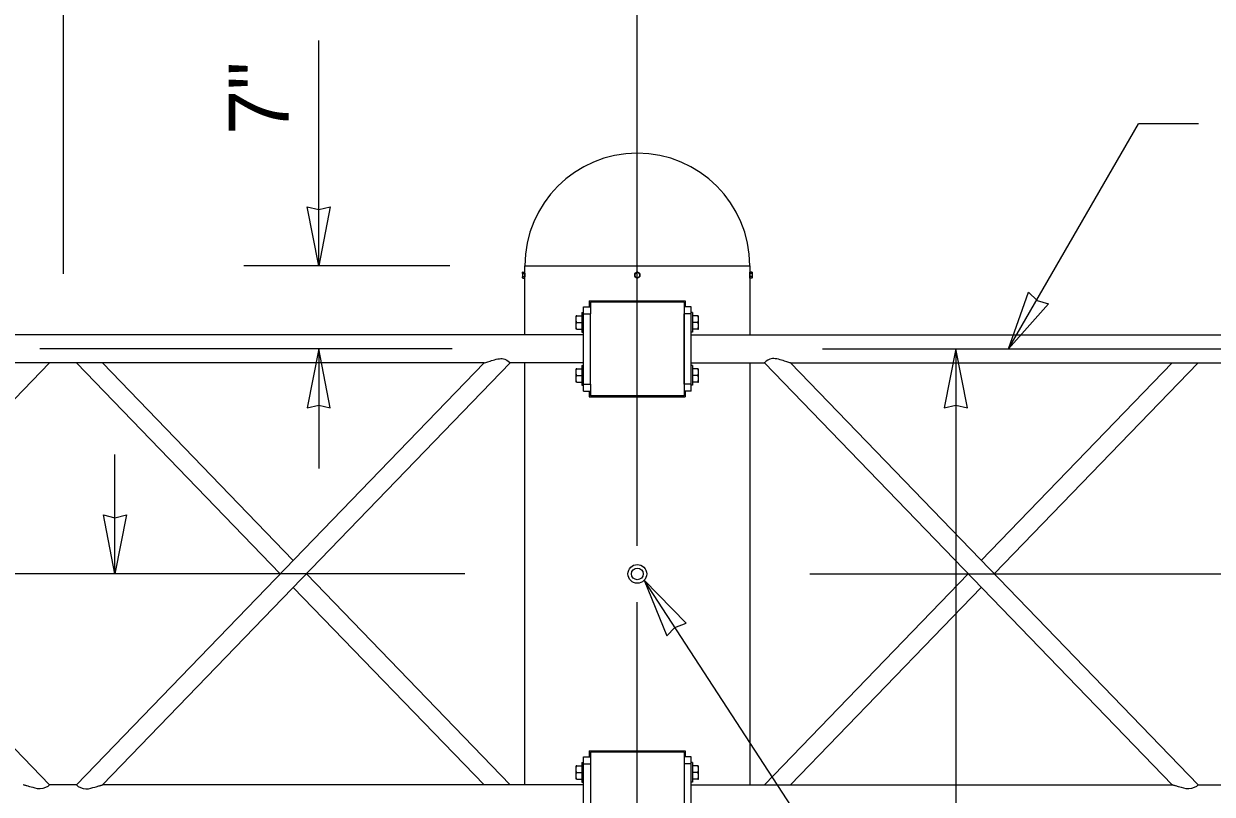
# Model space of a CAD drawing. Extents: x 99862 to 104211, y 98939 to 111076.
# Drawn here: x 101176.8 to 101493.9, y 104337.2 to 104542.6 of the extents above; entities that cross this region are included whole.
import ezdxf

# ---------------------------------------------------------------- set-up
doc = ezdxf.new("R2010")
doc.units = 0
for name, color, linetype in [('Level 15', 7, 'Continuous'), ('Level 20', 7, 'Continuous'), ('Level 3', 7, 'Continuous'), ('Level 4', 7, 'Continuous'), ('Level 5', 7, 'Continuous'), ('Level 6', 7, 'Continuous'), ('Level 9', 7, 'Continuous')]:
    doc.layers.add(name, color=color, linetype=linetype)

msp = doc.modelspace()

# ---------------------------------------------------------------- linework, layer by layer
at = {"layer": 'Level 15'}
for p, q in [((101187.43, 104475.89), (101187.43, 104720.89)), ((101340.5, 104403.39), (101340.5, 104615.2)), ((101255.5, 104478.08), (101255.5, 104538.08)), ((101439.57, 104455.89), (101474.21, 104515.89)), ((101490.21, 104515.89), (101474.21, 104515.89)), ((101290.5, 104478.08), (101235.5, 104478.08)), ((101291.12, 104455.89), (101181.12, 104455.89)), ((101255.5, 104455.89), (101255.5, 104424.01)), ((101389.87, 104455.89), (101540.24, 104455.89)), ((101425.5, 104455.89), (101425.5, 103662.4)), ((101201.12, 104395.89), (101201.12, 104427.77)), ((101294.5, 104395.89), (100703.11, 104395.89)), ((101386.5, 104395.89), (102303.88, 104395.89)), ((101519.55, 104122.56), (101342.34, 104394.21)), ((101340.5, 103587.9), (101340.5, 104388.39))]:
    msp.add_line(p, q, dxfattribs=at)
for points in [[(101255.5, 104478.08), (101252.41, 104493.8), (101255.5, 104493.08), (101258.58, 104493.8)], [(101439.57, 104455.89), (101444.88, 104471.01), (101447.17, 104468.82), (101450.2, 104467.88)], [(101255.5, 104455.89), (101252.41, 104440.17), (101255.5, 104440.89), (101258.58, 104440.17)], [(101425.5, 104455.89), (101422.41, 104440.17), (101425.5, 104440.89), (101428.58, 104440.17)], [(101201.12, 104395.89), (101198.04, 104411.62), (101201.12, 104410.89), (101204.21, 104411.62)], [(101342.34, 104394.21), (101348.35, 104379.35), (101350.54, 104381.65), (101353.52, 104382.72)]]:
    msp.add_lwpolyline(points, close=True, dxfattribs=at)
at = {"layer": 'Level 20'}
for p, q in [((101129.28, 104395.89), (101183.68, 104452.14)), ((101245.25, 104395.89), (101190.85, 104452.14)), ((101248.72, 104399.49), (101197.8, 104452.14)), ((101432.27, 104399.49), (101483.19, 104452.14)), ((101435.75, 104395.89), (101490.15, 104452.14)), ((101306.6, 104339.64), (101252.2, 104395.89)), ((101374.4, 104339.64), (101428.79, 104395.89)), ((101299.64, 104339.64), (101248.72, 104392.3)), ((101381.35, 104339.64), (101432.27, 104392.3))]:
    msp.add_line(p, q, dxfattribs=at)
at = {"layer": 'Level 3'}
for p, q in [((101310.5, 104476.39), (101310.5, 104478.08)), ((101370.5, 104478.08), (101370.5, 104459.64)), ((101310.5, 104459.64), (101310.5, 104474.77)), ((101327.68, 104468.7), (101327.68, 104467.14)), ((101327.68, 104468.7), (101353.31, 104468.7)), ((101353.31, 104468.7), (101353.31, 104467.14)), ((101310.5, 104339.64), (101310.5, 104452.14)), ((101370.5, 104452.14), (101370.5, 104339.64)), ((101327.68, 104444.64), (101327.68, 104443.08)), ((101327.68, 104443.08), (101353.31, 104443.08)), ((101353.31, 104444.64), (101353.31, 104443.08)), ((101327.68, 104348.7), (101353.31, 104348.7)), ((101327.68, 104348.7), (101327.68, 104347.14)), ((101353.31, 104348.7), (101353.31, 104347.14))]:
    msp.add_line(p, q, dxfattribs=at)
for radius in [2.5, 1.56]:
    msp.add_circle((101340.5, 104395.89), radius, dxfattribs=at)
for points in [[(101310.5, 104476.05), (101310.5, 104476.05), (101310.5, 104476.05), (101310.5, 104476.04), (101310.5, 104476.04), (101310.5, 104476.02), (101310.5, 104476), (101310.5, 104475.98), (101310.5, 104475.95), (101310.5, 104475.91), (101310.5, 104475.87), (101310.5, 104475.83), (101310.5, 104475.78), (101310.5, 104475.73), (101310.5, 104475.68), (101310.5, 104475.63), (101310.5, 104475.58), (101310.5, 104475.52), (101310.5, 104475.47), (101310.5, 104475.42), (101310.5, 104475.37), (101310.5, 104475.33), (101310.5, 104475.28), (101310.5, 104475.24), (101310.5, 104475.21), (101310.5, 104475.18), (101310.5, 104475.15), (101310.5, 104475.14), (101310.5, 104475.12), (101310.5, 104475.11), (101310.5, 104475.11)], [(101370.5, 104476.05), (101370.5, 104476.05), (101370.5, 104476.05), (101370.5, 104476.04), (101370.5, 104476.04), (101370.5, 104476.02), (101370.5, 104476), (101370.5, 104475.98), (101370.5, 104475.95), (101370.49, 104475.91), (101370.49, 104475.87), (101370.49, 104475.83), (101370.49, 104475.78), (101370.49, 104475.73), (101370.49, 104475.68), (101370.49, 104475.63), (101370.49, 104475.58), (101370.49, 104475.52), (101370.49, 104475.47), (101370.49, 104475.42), (101370.49, 104475.37), (101370.49, 104475.33), (101370.49, 104475.28), (101370.49, 104475.24), (101370.5, 104475.21), (101370.5, 104475.18), (101370.5, 104475.15), (101370.5, 104475.14), (101370.5, 104475.12), (101370.5, 104475.11), (101370.5, 104475.11)]]:
    msp.add_open_spline(points, degree=3, dxfattribs=at)
at = {"layer": 'Level 4'}
for p, q in [((101328, 104468.39), (101328, 104465.27)), ((101353, 104468.39), (101328, 104468.39)), ((101353, 104468.39), (101353, 104443.39)), ((101328, 104446.52), (101328, 104443.39)), ((101353, 104446.52), (101353, 104443.39)), ((101353, 104443.39), (101328, 104443.39)), ((101353, 104348.39), (101328, 104348.39)), ((101328, 104348.39), (101328, 104323.39)), ((101353, 104348.39), (101353, 104323.39))]:
    msp.add_line(p, q, dxfattribs=at)
at = {"layer": 'Level 5'}
for q in [(101310.5, 104478.08), (101370.5, 104478.08)]:
    msp.add_line((101310.5, 104478.08), q, dxfattribs=at)
msp.add_arc((101340.5, 104478.08), 30, 0, 180, dxfattribs=at)
at = {"layer": 'Level 6'}
for p, q in [((101370.5, 104474.77), (101370.5, 104475.17)), ((101371.06, 104475.17), (101370.5, 104475.17)), ((101371.06, 104474.77), (101370.5, 104474.77)), ((101371.12, 104474.88), (101371.06, 104474.77)), ((101326.12, 104467.14), (101328, 104467.14)), ((101326.12, 104444.64), (101326.12, 104467.14)), ((101326.12, 104465.27), (101328, 104465.27)), ((101328, 104446.52), (101328, 104465.27)), ((101354.87, 104467.14), (101353, 104467.14)), ((101353, 104446.52), (101353, 104465.27)), ((101354.87, 104465.27), (101353, 104465.27)), ((101354.87, 104444.64), (101354.87, 104467.14)), ((101326.12, 104459.64), (100443.11, 104459.64)), ((101354.87, 104459.64), (101687.88, 104459.64)), ((101074.88, 104452.14), (101183.68, 104339.64)), ((101299.64, 104452.14), (101074.88, 104452.14)), ((101299.64, 104452.14), (101190.85, 104339.64)), ((101306.6, 104452.14), (101197.8, 104339.64)), ((101326.12, 104452.14), (101306.6, 104452.14)), ((101354.87, 104452.14), (101374.4, 104452.14)), ((101374.4, 104452.14), (101483.19, 104339.64)), ((101381.35, 104452.14), (101490.15, 104339.64)), ((101381.35, 104452.14), (101606.11, 104452.14)), ((101326.12, 104446.52), (101328, 104446.52)), ((101354.87, 104446.52), (101353, 104446.52)), ((101326.12, 104444.64), (101328, 104444.64)), ((101354.87, 104444.64), (101353, 104444.64)), ((101326.12, 104347.14), (101328, 104347.14)), ((101326.12, 104324.64), (101326.12, 104347.14)), ((101326.12, 104345.27), (101328, 104345.27)), ((101354.87, 104347.14), (101353, 104347.14)), ((101354.87, 104345.27), (101353, 104345.27)), ((101354.87, 104324.64), (101354.87, 104347.14)), ((101190.85, 104339.64), (101183.67, 104339.64)), ((101326.12, 104339.64), (101197.8, 104339.64)), ((101354.87, 104339.64), (101483.19, 104339.64)), ((101490.14, 104339.64), (101497.32, 104339.64))]:
    msp.add_line(p, q, dxfattribs=at)
for points, degree in [([(101371.06, 104475.17), (101371.1, 104475.11), (101371.12, 104475.04), (101371.12, 104474.97)], 2), ([(101371.06, 104474.77), (101371.1, 104474.84), (101371.12, 104474.91), (101371.12, 104474.98), (101371.12, 104475.05), (101371.09, 104475.11), (101371.06, 104475.17)], 3), ([(101371.12, 104474.97), (101371.12, 104474.96), (101371.12, 104474.96), (101371.12, 104474.96), (101371.12, 104474.89), (101371.09, 104474.83), (101371.06, 104474.77)], 3), ([(101371.12, 104474.96), (101371.12, 104474.89), (101371.09, 104474.83), (101371.06, 104474.77)], 2), ([(101371.06, 104474.77), (101371.08, 104474.8), (101371.09, 104474.83), (101371.1, 104474.87)], 2), ([(101299.64, 104452.14), (101299.66, 104452.15), (101300.88, 104452.53), (101304.81, 104453.79), (101306.72, 104452.08), (101306.57, 104452.15), (101306.6, 104452.14)], 3), ([(101381.35, 104452.14), (101381.34, 104452.15), (101380.12, 104452.53), (101376.19, 104453.79), (101374.28, 104452.08), (101374.42, 104452.15), (101374.4, 104452.14)], 3), ([(101183.67, 104452.14), (101183.68, 104452.14), (101183.68, 104452.14), (101183.68, 104452.14)], 2), ([(101183.68, 104452.14), (101183.68, 104452.14), (101183.68, 104452.14), (101183.68, 104452.14)], 2), ([(101190.85, 104452.14), (101190.85, 104452.14), (101190.84, 104452.14), (101190.84, 104452.14)], 2), ([(101190.85, 104452.14), (101190.85, 104452.14), (101190.85, 104452.14), (101190.85, 104452.14)], 2), ([(101306.6, 104452.14), (101306.6, 104452.14), (101306.61, 104452.14), (101306.61, 104452.15)], 2), ([(101374.4, 104452.14), (101374.39, 104452.14), (101374.39, 104452.14), (101374.39, 104452.15)], 2), ([(101490.14, 104452.14), (101490.15, 104452.14), (101490.15, 104452.14), (101490.15, 104452.14)], 2), ([(101490.15, 104452.14), (101490.15, 104452.14), (101490.15, 104452.14), (101490.15, 104452.14)], 2), ([(101183.68, 104339.64), (101183.8, 104339.66), (101181.89, 104338.13), (101178.98, 104339), (101177.79, 104339.3), (101177.48, 104339.4), (101177.24, 104339.48), (101177.03, 104339.54), (101176.88, 104339.59), (101176.77, 104339.62), (101176.73, 104339.64), (101176.72, 104339.64), (101176.72, 104339.64), (101176.72, 104339.64)], 3), ([(101183.67, 104339.64), (101183.68, 104339.64), (101183.68, 104339.64), (101183.68, 104339.64)], 2), ([(101190.85, 104339.64), (101190.72, 104339.66), (101192.63, 104338.13), (101195.55, 104339), (101196.74, 104339.3), (101197.04, 104339.4), (101197.29, 104339.48), (101197.49, 104339.54), (101197.65, 104339.59), (101197.75, 104339.62), (101197.79, 104339.64), (101197.8, 104339.64), (101197.8, 104339.64), (101197.8, 104339.64)], 3), ([(101190.85, 104339.64), (101190.85, 104339.64), (101190.85, 104339.64), (101190.85, 104339.64)], 2), ([(101197.8, 104339.64), (101197.8, 104339.64), (101197.8, 104339.64), (101197.8, 104339.64)], 2), ([(101490.15, 104339.64), (101490.27, 104339.66), (101488.36, 104338.13), (101485.45, 104339), (101484.26, 104339.3), (101483.95, 104339.4), (101483.71, 104339.48), (101483.5, 104339.54), (101483.35, 104339.59), (101483.24, 104339.62), (101483.2, 104339.64), (101483.19, 104339.64), (101483.19, 104339.64), (101483.19, 104339.64)], 3), ([(101483.19, 104339.64), (101483.19, 104339.64), (101483.19, 104339.64), (101483.19, 104339.64)], 2), ([(101490.14, 104339.64), (101490.15, 104339.64), (101490.15, 104339.64), (101490.15, 104339.64)], 2)]:
    msp.add_open_spline(points, degree=degree, dxfattribs=at)
at = {"layer": 'Level 9'}
for p, q in [((101309.87, 104476.28), (101309.93, 104476.39)), ((101309.87, 104476.28), (101309.87, 104476.2)), ((101309.87, 104476.18), (101309.87, 104476.2)), ((101309.87, 104476.18), (101309.87, 104475.58)), ((101309.87, 104475.58), (101309.87, 104474.88)), ((101309.93, 104474.77), (101309.87, 104474.88)), ((101309.93, 104476.39), (101310.5, 104476.39)), ((101309.93, 104475.98), (101310.5, 104475.98)), ((101309.93, 104475.17), (101310.5, 104475.17)), ((101309.93, 104474.77), (101310.5, 104474.77)), ((101310.5, 104475.98), (101310.5, 104476.39)), ((101310.5, 104475.17), (101310.5, 104475.98)), ((101310.5, 104474.77), (101310.5, 104475.17)), ((101339.79, 104475.6), (101339.79, 104475.56)), ((101340.16, 104476.2), (101340.13, 104476.18)), ((101340.14, 104474.97), (101340.15, 104474.97)), ((101340.86, 104476.18), (101340.84, 104476.2)), ((101370.5, 104475.98), (101370.5, 104476.39)), ((101371.06, 104476.39), (101370.5, 104476.39)), ((101370.5, 104475.17), (101370.5, 104475.98)), ((101371.06, 104475.98), (101370.5, 104475.98)), ((101371.06, 104476.39), (101371.12, 104476.28)), ((101371.12, 104476.28), (101371.12, 104476.2)), ((101371.12, 104476.18), (101371.12, 104476.2)), ((101371.12, 104476.18), (101371.12, 104475.58)), ((101371.12, 104475.58), (101371.12, 104474.88)), ((101325.73, 104465.57), (101325.73, 104460.36)), ((101325.73, 104465.57), (101326.12, 104465.57)), ((101355.26, 104465.57), (101354.87, 104465.57)), ((101355.26, 104465.57), (101355.26, 104460.36)), ((101324.17, 104463.87), (101324.17, 104464.71)), ((101324.17, 104463.79), (101324.17, 104463.87)), ((101324.17, 104462.11), (101324.17, 104463.79)), ((101324.17, 104462.04), (101324.17, 104462.11)), ((101324.17, 104461.19), (101324.17, 104462.04)), ((101324.33, 104464.71), (101325.73, 104464.71)), ((101324.33, 104462.95), (101325.73, 104462.95)), ((101356.67, 104464.71), (101355.26, 104464.71)), ((101356.67, 104462.95), (101355.26, 104462.95)), ((101356.82, 104463.87), (101356.82, 104464.71)), ((101356.82, 104463.79), (101356.82, 104463.87)), ((101356.82, 104462.11), (101356.82, 104463.79)), ((101356.82, 104462.04), (101356.82, 104462.11)), ((101356.82, 104461.19), (101356.82, 104462.04)), ((101324.33, 104461.19), (101325.73, 104461.19)), ((101325.73, 104460.36), (101326.12, 104460.36)), ((101355.26, 104460.36), (101354.87, 104460.36)), ((101356.67, 104461.19), (101355.26, 104461.19)), ((101324.17, 104449.73), (101324.17, 104450.57)), ((101324.17, 104449.65), (101324.17, 104449.73)), ((101324.17, 104447.96), (101324.17, 104449.65)), ((101324.33, 104450.57), (101325.73, 104450.57)), ((101325.73, 104451.42), (101325.73, 104446.22)), ((101325.73, 104451.42), (101326.12, 104451.42)), ((101355.26, 104451.42), (101354.87, 104451.42)), ((101355.26, 104451.42), (101355.26, 104446.22)), ((101356.67, 104450.57), (101355.26, 104450.57)), ((101356.82, 104449.73), (101356.82, 104450.57)), ((101356.82, 104449.65), (101356.82, 104449.73)), ((101356.82, 104447.96), (101356.82, 104449.65)), ((101324.17, 104447.9), (101324.17, 104447.96)), ((101324.17, 104447.05), (101324.17, 104447.9)), ((101324.33, 104448.81), (101325.73, 104448.81)), ((101324.33, 104447.05), (101325.73, 104447.05)), ((101325.73, 104446.22), (101326.12, 104446.22)), ((101355.26, 104446.22), (101354.87, 104446.22)), ((101356.67, 104448.81), (101355.26, 104448.81)), ((101356.67, 104447.05), (101355.26, 104447.05)), ((101356.82, 104447.9), (101356.82, 104447.96)), ((101356.82, 104447.05), (101356.82, 104447.9)), ((101324.17, 104343.87), (101324.17, 104344.71)), ((101324.33, 104344.71), (101325.73, 104344.71)), ((101325.73, 104345.57), (101325.73, 104340.36)), ((101325.73, 104345.57), (101326.12, 104345.57)), ((101355.26, 104345.57), (101354.87, 104345.57)), ((101355.26, 104345.57), (101355.26, 104340.36)), ((101356.67, 104344.71), (101355.26, 104344.71)), ((101356.82, 104343.87), (101356.82, 104344.71)), ((101324.17, 104343.79), (101324.17, 104343.87)), ((101324.17, 104342.11), (101324.17, 104343.79)), ((101324.17, 104342.04), (101324.17, 104342.11)), ((101324.17, 104341.19), (101324.17, 104342.04)), ((101324.33, 104342.95), (101325.73, 104342.95)), ((101356.67, 104342.95), (101355.26, 104342.95)), ((101356.82, 104343.79), (101356.82, 104343.87)), ((101356.82, 104342.11), (101356.82, 104343.79)), ((101356.82, 104342.04), (101356.82, 104342.11)), ((101356.82, 104341.19), (101356.82, 104342.04)), ((101324.33, 104341.19), (101325.73, 104341.19)), ((101325.73, 104340.36), (101326.12, 104340.36)), ((101355.26, 104340.36), (101354.87, 104340.36)), ((101356.67, 104341.19), (101355.26, 104341.19))]:
    msp.add_line(p, q, dxfattribs=at)
for start, end in [(121.5608, 178.5832), (181.4168, 239.242), (240.7554, 0), (61.1969, 118.4392), (0, 58.8031)]:
    msp.add_arc((101340.5, 104475.58), 0.703, start, end, dxfattribs=at)
for points, degree in [([(101309.87, 104476.2), (101309.87, 104476.2), (101309.87, 104476.2), (101309.87, 104476.2), (101309.88, 104476.27), (101309.9, 104476.33), (101309.93, 104476.39)], 3), ([(101309.93, 104475.98), (101309.9, 104476.05), (101309.87, 104476.11), (101309.87, 104476.18)], 2), ([(101309.93, 104475.98), (101309.93, 104475.95), (101309.92, 104475.92), (101309.91, 104475.89), (101309.89, 104475.79), (101309.87, 104475.68), (101309.87, 104475.58)], 3), ([(101309.87, 104475.58), (101309.87, 104475.54), (101309.87, 104475.51), (101309.88, 104475.47), (101309.88, 104475.37), (101309.91, 104475.27), (101309.93, 104475.17)], 3), ([(101309.93, 104474.77), (101309.89, 104474.84), (101309.87, 104474.91), (101309.87, 104474.98), (101309.88, 104475.05), (101309.9, 104475.11), (101309.93, 104475.17)], 3), ([(101309.87, 104474.96), (101309.88, 104474.89), (101309.9, 104474.83), (101309.93, 104474.77)], 2), ([(101309.93, 104476.39), (101309.91, 104476.35), (101309.89, 104476.31), (101309.88, 104476.27)], 2), ([(101340.13, 104476.18), (101340.13, 104476.18), (101340.12, 104476.18), (101340.12, 104476.17), (101340.01, 104476.11), (101339.9, 104476.05), (101339.79, 104475.98)], 3), ([(101339.79, 104475.98), (101339.79, 104475.95), (101339.79, 104475.92), (101339.79, 104475.89), (101339.79, 104475.79), (101339.79, 104475.7), (101339.79, 104475.6)], 3), ([(101339.79, 104475.56), (101339.79, 104475.53), (101339.79, 104475.5), (101339.79, 104475.48), (101339.79, 104475.37), (101339.79, 104475.27), (101339.79, 104475.17)], 3), ([(101339.79, 104475.17), (101339.91, 104475.11), (101340.02, 104475.04), (101340.14, 104474.97)], 2), ([(101340.15, 104474.97), (101340.16, 104474.96), (101340.16, 104474.96), (101340.17, 104474.96), (101340.28, 104474.89), (101340.39, 104474.83), (101340.5, 104474.77)], 3), ([(101340.5, 104476.39), (101340.39, 104476.33), (101340.28, 104476.26), (101340.16, 104476.2)], 2), ([(101340.84, 104476.2), (101340.83, 104476.2), (101340.83, 104476.2), (101340.82, 104476.2), (101340.71, 104476.27), (101340.6, 104476.33), (101340.5, 104476.39)], 3), ([(101340.5, 104474.77), (101340.62, 104474.84), (101340.75, 104474.91), (101340.87, 104474.98), (101340.98, 104475.05), (101341.09, 104475.11), (101341.2, 104475.17)], 3), ([(101341.2, 104475.98), (101341.09, 104476.05), (101340.98, 104476.11), (101340.86, 104476.18)], 2), ([(101341.2, 104475.98), (101341.2, 104475.95), (101341.2, 104475.92), (101341.2, 104475.89), (101341.2, 104475.79), (101341.2, 104475.68), (101341.2, 104475.58)], 3), ([(101341.2, 104475.58), (101341.2, 104475.54), (101341.2, 104475.51), (101341.2, 104475.47), (101341.2, 104475.37), (101341.2, 104475.27), (101341.2, 104475.17)], 3), ([(101371.12, 104476.25), (101371.11, 104476.3), (101371.09, 104476.34), (101371.06, 104476.39)], 2), ([(101371.06, 104476.39), (101371.1, 104476.33), (101371.12, 104476.26), (101371.12, 104476.2)], 2), ([(101371.06, 104476.39), (101371.08, 104476.35), (101371.1, 104476.31), (101371.11, 104476.27)], 2), ([(101371.12, 104476.2), (101371.12, 104476.2), (101371.12, 104476.2), (101371.12, 104476.2), (101371.12, 104476.27), (101371.09, 104476.33), (101371.06, 104476.39)], 3), ([(101371.12, 104476.18), (101371.12, 104476.18), (101371.12, 104476.18), (101371.12, 104476.17), (101371.12, 104476.11), (101371.09, 104476.05), (101371.06, 104475.98)], 3), ([(101371.06, 104475.98), (101371.1, 104476.05), (101371.12, 104476.11), (101371.12, 104476.18)], 2), ([(101371.06, 104475.98), (101371.07, 104475.95), (101371.08, 104475.92), (101371.08, 104475.89), (101371.11, 104475.79), (101371.12, 104475.68), (101371.12, 104475.58)], 3), ([(101371.06, 104475.98), (101371.07, 104475.95), (101371.08, 104475.92), (101371.08, 104475.89), (101371.11, 104475.79), (101371.12, 104475.7), (101371.12, 104475.6)], 3), ([(101371.06, 104475.98), (101371.07, 104475.95), (101371.08, 104475.92), (101371.08, 104475.89), (101371.11, 104475.79), (101371.12, 104475.68), (101371.12, 104475.58)], 3), ([(101371.12, 104475.58), (101371.12, 104475.54), (101371.12, 104475.51), (101371.12, 104475.47), (101371.11, 104475.37), (101371.09, 104475.27), (101371.06, 104475.17)], 3), ([(101371.12, 104475.58), (101371.12, 104475.54), (101371.12, 104475.51), (101371.12, 104475.47), (101371.11, 104475.37), (101371.09, 104475.27), (101371.06, 104475.17)], 3), ([(101371.12, 104475.56), (101371.12, 104475.53), (101371.12, 104475.5), (101371.12, 104475.48), (101371.11, 104475.37), (101371.09, 104475.27), (101371.06, 104475.17)], 3), ([(101324.33, 104464.71), (101324.23, 104464.71), (101324.17, 104464.71), (101324.17, 104464.71)], 2), ([(101324.17, 104463.87), (101324.17, 104464.16), (101324.23, 104464.44), (101324.33, 104464.71)], 2), ([(101324.33, 104462.95), (101324.23, 104463.23), (101324.17, 104463.5), (101324.17, 104463.79)], 2), ([(101324.17, 104462.11), (101324.17, 104462.39), (101324.23, 104462.68), (101324.33, 104462.95)], 2), ([(101324.33, 104461.19), (101324.23, 104461.47), (101324.17, 104461.75), (101324.17, 104462.04)], 2), ([(101356.67, 104464.71), (101356.76, 104464.71), (101356.82, 104464.71), (101356.82, 104464.71)], 2), ([(101356.82, 104463.87), (101356.82, 104464.16), (101356.76, 104464.44), (101356.67, 104464.71)], 2), ([(101356.67, 104462.95), (101356.76, 104463.23), (101356.82, 104463.5), (101356.82, 104463.79)], 2), ([(101356.82, 104462.11), (101356.82, 104462.39), (101356.76, 104462.68), (101356.67, 104462.95)], 2), ([(101356.67, 104461.19), (101356.76, 104461.47), (101356.82, 104461.75), (101356.82, 104462.04)], 2), ([(101324.17, 104461.19), (101324.17, 104461.19), (101324.17, 104461.19), (101324.17, 104461.19)], 2), ([(101324.33, 104461.19), (101324.23, 104461.19), (101324.17, 104461.19), (101324.17, 104461.19)], 2), ([(101356.67, 104461.19), (101356.76, 104461.19), (101356.82, 104461.19), (101356.82, 104461.19)], 2), ([(101356.82, 104461.19), (101356.82, 104461.19), (101356.82, 104461.19), (101356.82, 104461.19)], 2), ([(101324.33, 104450.57), (101324.23, 104450.57), (101324.17, 104450.57), (101324.17, 104450.57)], 2), ([(101324.17, 104449.73), (101324.17, 104450.02), (101324.23, 104450.29), (101324.33, 104450.57)], 2), ([(101324.33, 104448.81), (101324.23, 104449.08), (101324.17, 104449.36), (101324.17, 104449.65)], 2), ([(101356.67, 104450.57), (101356.76, 104450.57), (101356.82, 104450.57), (101356.82, 104450.57)], 2), ([(101356.82, 104449.73), (101356.82, 104450.02), (101356.76, 104450.29), (101356.67, 104450.57)], 2), ([(101356.67, 104448.81), (101356.76, 104449.08), (101356.82, 104449.36), (101356.82, 104449.65)], 2), ([(101324.17, 104447.96), (101324.17, 104448.25), (101324.23, 104448.53), (101324.33, 104448.81)], 2), ([(101324.33, 104447.05), (101324.23, 104447.33), (101324.17, 104447.61), (101324.17, 104447.9)], 2), ([(101324.17, 104447.05), (101324.17, 104447.05), (101324.17, 104447.05), (101324.17, 104447.05)], 2), ([(101324.33, 104447.05), (101324.23, 104447.05), (101324.17, 104447.05), (101324.17, 104447.05)], 2), ([(101356.82, 104447.96), (101356.82, 104448.25), (101356.76, 104448.53), (101356.67, 104448.81)], 2), ([(101356.67, 104447.05), (101356.76, 104447.33), (101356.82, 104447.61), (101356.82, 104447.9)], 2), ([(101356.67, 104447.05), (101356.76, 104447.05), (101356.82, 104447.05), (101356.82, 104447.05)], 2), ([(101356.82, 104447.05), (101356.82, 104447.05), (101356.82, 104447.05), (101356.82, 104447.05)], 2), ([(101324.33, 104344.71), (101324.23, 104344.71), (101324.17, 104344.71), (101324.17, 104344.71)], 2), ([(101324.17, 104343.87), (101324.17, 104344.16), (101324.23, 104344.44), (101324.33, 104344.71)], 2), ([(101356.67, 104344.71), (101356.76, 104344.71), (101356.82, 104344.71), (101356.82, 104344.71)], 2), ([(101356.82, 104343.87), (101356.82, 104344.16), (101356.76, 104344.44), (101356.67, 104344.71)], 2), ([(101324.33, 104342.95), (101324.23, 104343.23), (101324.17, 104343.5), (101324.17, 104343.79)], 2), ([(101324.17, 104342.11), (101324.17, 104342.39), (101324.23, 104342.68), (101324.33, 104342.95)], 2), ([(101324.33, 104341.19), (101324.23, 104341.47), (101324.17, 104341.75), (101324.17, 104342.04)], 2), ([(101356.67, 104342.95), (101356.76, 104343.23), (101356.82, 104343.5), (101356.82, 104343.79)], 2), ([(101356.82, 104342.11), (101356.82, 104342.39), (101356.76, 104342.68), (101356.67, 104342.95)], 2), ([(101356.67, 104341.19), (101356.76, 104341.47), (101356.82, 104341.75), (101356.82, 104342.04)], 2), ([(101324.17, 104341.19), (101324.17, 104341.19), (101324.17, 104341.19), (101324.17, 104341.19)], 2), ([(101324.33, 104341.19), (101324.23, 104341.19), (101324.17, 104341.19), (101324.17, 104341.19)], 2), ([(101356.67, 104341.19), (101356.76, 104341.19), (101356.82, 104341.19), (101356.82, 104341.19)], 2), ([(101356.82, 104341.19), (101356.82, 104341.19), (101356.82, 104341.19), (101356.82, 104341.19)], 2)]:
    msp.add_open_spline(points, degree=degree, dxfattribs=at)

# ---------------------------------------------------------------- texts
at = {"layer": 'Level 20'}
msp.add_text('7"', height=16, rotation=90, dxfattribs=at).set_placement((101247.5, 104512.99))

doc.saveas('drawing.dxf')
